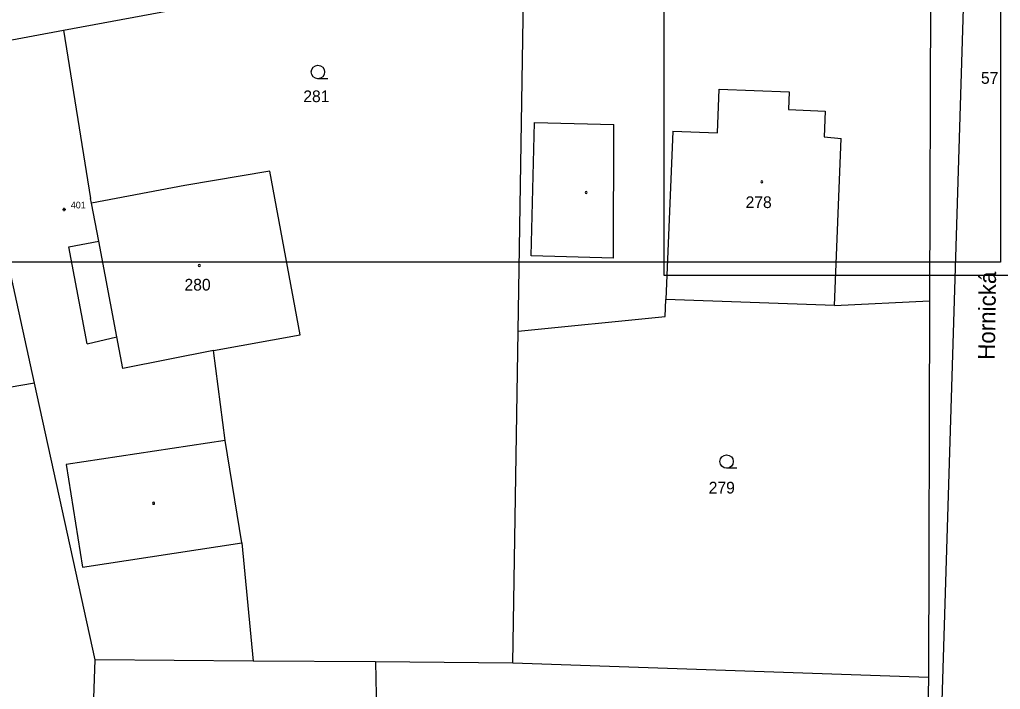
# Model space of a CAD drawing. Extents: x -454285 to -453563, y -1108687 to -1108249.
# Drawn here: x -453927.9 to -453869.2, y -1108526.5 to -1108486.5 of the extents above; entities that cross this region are included whole.
import ezdxf

# ---------------------------------------------------------------- set-up
doc = ezdxf.new("R2010")
doc.units = 0
for name, color, linetype in [('1', 7, 'Continuous'), ('14', 7, 'Continuous'), ('15', 7, 'Continuous'), ('2', 7, 'Continuous'), ('23', 7, 'Continuous'), ('25', 7, 'Continuous'), ('38', 7, 'Continuous'), ('BODY_T1_2018', 7, 'Continuous'), ('CISLA_T1_2018', 7, 'Continuous'), ('rámy', 7, 'Continuous')]:
    doc.layers.add(name, color=color, linetype=linetype)

# ---------------------------------------------------------------- blocks, each defined once
blk = doc.blocks.new('Z402')
for start, end in [(0, 180), (180, 0)]:
    blk.add_arc((0, 0), 0.15, start, end)
blk = doc.blocks.new('Z3040')
blk.add_line((1.5, 0), (0, 0))
blk.add_circle((0, 1), 1)
blk = doc.blocks.new('POINT_DISPLAY')
for p, q in [((-0.1, 0), (0.1, 0)), ((0, -0.1), (0, 0.1))]:
    blk.add_line(p, q)
blk.add_circle((0, 0), 0.05)
blk = doc.blocks.new('t1_2018')
at = {"layer": 'BODY_T1_2018'}
blk.add_blockref('POINT_DISPLAY', (-453925.19, -1108497.8), dxfattribs=at)
at = {"layer": 'CISLA_T1_2018'}
blk.add_text('401', height=0.4, dxfattribs=at).set_placement((-453924.79, -1108497.74))

msp = doc.modelspace()

# ---------------------------------------------------------------- linework, layer by layer
at = {"layer": '1'}
for p, q in [((-453873.387, -1108481.541), (-453873.447, -1108503.261)), ((-453925.217, -1108487.081), (-453897.667, -1108481.961)), ((-453898.037, -1108505.081), (-453897.667, -1108481.961)), ((-453931.337, -1108488.221), (-453925.217, -1108487.081)), ((-453925.217, -1108487.081), (-453923.617, -1108497.151)), ((-453926.957, -1108508.191), (-453931.337, -1108488.221)), ((-453912.897, -1108495.521), (-453917.967, -1108496.371)), ((-453911.067, -1108505.291), (-453912.897, -1108495.521)), ((-453917.967, -1108496.371), (-453923.547, -1108497.431)), ((-453923.547, -1108497.431), (-453923.617, -1108497.151)), ((-453889.247, -1108504.201), (-453889.207, -1108503.181)), ((-453879.127, -1108503.541), (-453889.207, -1108503.181)), ((-453879.127, -1108503.541), (-453873.447, -1108503.261)), ((-453873.447, -1108503.261), (-453873.507, -1108525.781)), ((-453898.037, -1108505.081), (-453889.247, -1108504.201)), ((-453898.357, -1108524.921), (-453898.037, -1108505.081)), ((-453916.257, -1108506.241), (-453911.067, -1108505.291)), ((-453915.567, -1108511.621), (-453916.257, -1108506.241)), ((-453926.957, -1108508.191), (-453929.677, -1108508.651)), ((-453923.337, -1108524.721), (-453926.957, -1108508.191)), ((-453914.557, -1108517.731), (-453915.567, -1108511.621)), ((-453914.557, -1108517.731), (-453913.877, -1108524.801)), ((-453923.427, -1108527.581), (-453923.337, -1108524.721)), ((-453913.877, -1108524.801), (-453923.337, -1108524.721)), ((-453906.577, -1108524.851), (-453913.877, -1108524.801)), ((-453898.357, -1108524.921), (-453906.577, -1108524.851)), ((-453906.577, -1108524.851), (-453906.417, -1108533.071)), ((-453873.507, -1108525.781), (-453898.357, -1108524.921)), ((-453873.507, -1108525.781), (-453873.857, -1108540.391))]:
    msp.add_line(p, q, dxfattribs=at)
at = {"layer": '2'}
for p, q in [((-453871.397, -1108484.241), (-453873.167, -1108541.891)), ((-453886.117, -1108493.221), (-453886.017, -1108490.601)), ((-453886.017, -1108490.601), (-453881.847, -1108490.771)), ((-453881.847, -1108490.771), (-453881.887, -1108491.831)), ((-453881.887, -1108491.831), (-453879.687, -1108491.921)), ((-453879.687, -1108491.921), (-453879.747, -1108493.451)), ((-453897.267, -1108500.581), (-453897.067, -1108492.611)), ((-453897.067, -1108492.611), (-453892.327, -1108492.731)), ((-453892.337, -1108500.711), (-453892.327, -1108492.731)), ((-453888.797, -1108493.111), (-453889.207, -1108503.181)), ((-453888.797, -1108493.111), (-453886.117, -1108493.221)), ((-453879.747, -1108493.451), (-453878.727, -1108493.551)), ((-453879.127, -1108503.541), (-453878.727, -1108493.551)), ((-453923.117, -1108499.691), (-453923.547, -1108497.431)), ((-453924.907, -1108500.031), (-453923.117, -1108499.691)), ((-453922.047, -1108505.411), (-453923.117, -1108499.691)), ((-453923.817, -1108505.831), (-453924.907, -1108500.031)), ((-453892.337, -1108500.711), (-453897.267, -1108500.581)), ((-453923.817, -1108505.831), (-453922.047, -1108505.411)), ((-453921.687, -1108507.301), (-453922.047, -1108505.411)), ((-453916.257, -1108506.241), (-453921.687, -1108507.301)), ((-453915.567, -1108511.621), (-453925.067, -1108513.051)), ((-453925.067, -1108513.051), (-453924.087, -1108519.181)), ((-453924.087, -1108519.181), (-453914.557, -1108517.731))]:
    msp.add_line(p, q, dxfattribs=at)
at = {"layer": 'rámy'}
for points in [[(-453968.38, -1108440.904), (-453869.211, -1108440.904), (-453869.211, -1108500.955), (-453968.38, -1108500.955)], [(-453889.309, -1108441.707), (-453790.141, -1108441.707), (-453790.141, -1108501.759), (-453889.309, -1108501.759)]]:
    msp.add_lwpolyline(points, close=True, dxfattribs=at)

# ---------------------------------------------------------------- block references
msp.add_blockref('t1_2018', (0, 0))
at = {"layer": '23', "xscale": 0.4, "yscale": 0.4000000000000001}
for p in [(-453910.012, -1108489.982), (-453885.577, -1108513.271)]:
    msp.add_blockref('Z3040', p, dxfattribs=at)
at = {"layer": '25', "xscale": 0.4, "yscale": 0.4000000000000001}
for p in [(-453883.477, -1108496.151), (-453893.977, -1108496.781), (-453917.105, -1108501.149), (-453919.837, -1108515.371)]:
    msp.add_blockref('Z402', p, dxfattribs=at)

# ---------------------------------------------------------------- texts
at = {"layer": '14'}
for s, p in [('57', (-453870.37, -1108490.291)), ('281', (-453910.889, -1108491.386)), ('279', (-453886.649, -1108514.784))]:
    msp.add_text(s, height=0.7, dxfattribs=at).set_placement(p)
at = {"layer": '15'}
for s, p in [('278', (-453884.443, -1108497.719)), ('280', (-453917.992, -1108502.651))]:
    msp.add_text(s, height=0.7, dxfattribs=at).set_placement(p)
at = {"layer": '38'}
msp.add_text('Hornická', height=1, rotation=89.091, dxfattribs=at).set_placement((-453869.547, -1108506.801))

doc.saveas('drawing.dxf')
